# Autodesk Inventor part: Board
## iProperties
Shininess: 64.0
Length Units: 11272
Angle Units: 11279
Time Units: 11290
Mass Units: 11286
Length Display Precision: 3
Angle Display Precision: 2
Compacted: True
Part Number: Board
Document SubType Name: Modeling
Created: 2006-08
Designer: jpalmisano
Manufacturer: Standard
Standards Organization: Custom
Material: Delrin, Black
Mass: 10.2008 g
Surface Area: 89.117 cm^2
Volume: 7.15846 cm^3
Density: 1.425 g/cm^3
Density: 0.0
Volumn: 0.0
Area: 0.0
PropertySet Name: Model Information
Control State: 0
Master: False
Checked Out: False
Author: jpalmisano
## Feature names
1. Extrusion1
2. Hole1
3. Extrusion2
4. Extrusion3
5. Extrusion4
6. Extrusion5
7. Extrusion6
8. Extrusion7
